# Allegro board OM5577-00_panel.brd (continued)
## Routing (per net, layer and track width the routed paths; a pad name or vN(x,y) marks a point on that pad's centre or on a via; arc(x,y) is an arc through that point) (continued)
A_1_I2C_SCL: length 42.9
  IS1 w0.15: v2(32.2,174.1) 31.65,174.65 28.2,174.65 27.2,175.65 v3(27.2,175.8)
  IS2 w0.5: A_1_TB3.2 8.66,178.24 9.6,177.3 9.6,176.05 12.3,173.35 31.45,173.35 v2(32.2,174.1) 37.9,174.1 40.01,176.21 A_1_TB2.2
A_1_I2C_SDA: length 39
  TOP w0.2: v2(28.3,175.4) 28.3,175.6 27.6,176.3 A_1_U1.C1
  IS2 w0.5: A_1_TB3.3 9.57,180.78 15.1,175.25 21.7,175.25 21.95,175.5 28.2,175.5 v2(28.3,175.4) 30.5,175.4 31,174.9 34.55,174.9 38.4,178.75 A_1_TB2.3
A_1_IRQ: length 39.8
  TOP w0.2: A_1_U1.D1 28,176.8 28.3,176.5 v2(28.3,176.6)
  IS2 w0.5: A_1_TB2.4 38.84,181.29 33.5,175.95 31.35,175.95 30.8,176.5 28.4,176.5 v2(28.3,176.6) 28.2,176.5 22.25,176.5 21.8,176.95 16,176.95 9.63,183.32 A_1_TB3.4
A_1_N2189999: length 7.7
  TOP w0.5: 28.1,186.27 28.1,187.8 A_1_C50.1 A_1_C17.1 A_1_R55.1 ; 28.1,186.27 A_1_C54.2 ; 28.1,186.27 A_1_C15.2 A_1_R53.2
A_1_N2190055: length 7.8
  TOP w0.5: A_1_R54.2 A_1_C16.2 23.3,186.27 ; 23.3,186.27 23.3,187.8 A_1_C51.2 A_1_C18.2 A_1_R56.1 ; 23.3,186.27 A_1_C55.2
A_1_N2190079: length 6.3
  TOP w0.5: A_1_C54.1 28.15,184.7 ; 28.15,184.7 28.15,183.1 A_1_R1.1 A_1_C13.1 28.04,181.56 A_1_L1.2 ; 28.15,184.7 A_1_C15.1
A_1_N2190159: length 11.7
  TOP w0.5: A_1_TB1.3 21.59,194.2 A_1_R73.1 arc(20.64,191.93) A_1_R56.2 arc(20.04,188.9) 19.95,188.42 A_1_C12.2 A_1_C52.2
A_1_N2190199: length 11.7
  TOP w0.5: A_1_TB1.1 29.81,194.2 29.81,194.4 arc(30.76,191.93) A_1_R55.2 arc(31.36,188.9) 31.45,188.42 A_1_C11.2 A_1_C53.2
A_1_N2190513: length 6.3
  TOP w0.5: 23.25,184.7 23.25,183.2 A_1_R2.2 23.37,181.65 A_1_C14.2 23.36,181.54 23.33,180.05 ; 23.25,184.7 A_1_C55.1 ; 23.25,184.7 A_1_C16.1
A_1_N2190991: length 583.3
  TOP w0.5: v2(24.1,196.5) 7.5,196.5 7.5,232.4 26.05,232.4 27.05,231.5 43.25,231.5 43.25,197.4 8.25,197.4 8.25,231.5 v2(25.7,231.5) ; v2(25.7,233.3) 6.75,233.3 6.75,195.6 24.45,195.6 25.45,196.5 44,196.5 44,232.4 v2(27.3,232.4) ; A_1_L104.2 6,194.7 6,234.2 25.95,234.2 26.95,233.3 44.75,233.3 44.75,195.6 v2(25.7,195.6) ; v2(27.3,234.15) 27.3,234.2 45.5,234.2 45.5,194.7 A_1_L104.1
  BOTTOM w0.5: v2(25.7,195.6) v2(24.1,196.5) ; v2(25.7,233.3) v2(27.3,234.15) ; v2(27.3,232.4) v2(25.7,231.5)
A_1_N2198580: length 7.5
  TOP w0.2: v2(31.1,174.1) 31.1,174.3 30.7,174.7 30.24,174.7 30.21,174.67 ; 30.21,174.67 A_1_R23.1 ; 30.21,174.67 A_1_R24.2
  IS1 w0.15: v3(26.7,175.8) 26.7,175.65 28.25,174.1 v2(31.1,174.1)
A_1_N2222470: length 3.3
  TOP w0.5: A_1_C20.2 A_1_R2.1 21.7,183.2 21.7,184.7 A_1_R54.1
A_1_N2227379: length 3.3
  TOP w0.5: A_1_R53.1 29.7,184.7 29.7,183.1 A_1_R1.2 A_1_C19.2
A_1_N2256986: length 4.6
  TOP w0.25: A_1_U1.A3 26.2,174.6 26.45,174.35 26.75,174.35 27.45,173.65 A_1_C57.1 27.29,172.85 26.95,172.85 26.65,172.55 26.5,172.55 26.23,172.28 A_1_Y1.3
A_1_N2256988: length 4.4
  TOP w0.25: A_1_C56.1 25.11,173.51 A_1_Y1.1 v2(25.18,174.53)
  IS1 w0.25: v3(26.2,176.3) 26.2,176.15 25.7,175.65 25.7,175.05 v2(25.18,174.53)
A_1_N2257197: length 1.7
  TOP w0.2: A_1_R32.2 27.99,174.51 A_1_U1.A1
A_1_N2257995: length 4.2
  TOP w0.25: A_1_C1.1 A_1_C22.1 23.06,174.45 23.45,174.45 v2(23.7,174.7)
  IS1 w0.25: v2(23.7,174.7) 23.7,175.7 24.3,176.3 v3(24.7,176.3)
A_1_N2259746: length 5
  TOP w0.25: A_1_C10.1 20.14,178 22.8,178 22.91,177.89 A_1_C7.1 A_1_U1.E7
A_1_N2259753: length 1.5
  TOP w0.25: A_1_C8.1 23.01,176.4 23.35,176.4 23.75,176.8 A_1_U1.D7
A_1_N2259760: length 1.9
  TOP w0.25: A_1_U1.F7 23.85,177.8 23.55,178.1 23.55,178.5 23.35,178.7 A_1_C6.1
A_1_PVDD: length 62.1
  TOP w0.2: A_1_R23.2 A_1_C3.1
  TOP w0.25: A_1_C2.1 23.35,175.3 23.65,175.6 23.65,176 23.95,176.3 A_1_U1.C7 ; A_1_U1.G1 27.5,178.3 27.9,178.7 A_1_C21.1 A_1_C9.1
  TOP w0.3: A_1_U1.G2 A_1_U1.G1
  TOP w0.5: v2(33.35,172.9) 33.35,176.7 32.35,177.7 v2(31.7,177.7)
  IS1 w0.25: v3(29.35,176.7) v3(29.05,176.7) 28.95,176.7 28.89,176.76 28.89,176.84 28.54,177.19 27.98,177.19 27.6,176.8 v3(26.2,176.8)
  IS1 w0.3: v3(29.35,176.7) 29.35,177.4 29.05,177.7 v3(28.65,177.7) v3(28.35,177.7) ; v3(22.75,175.1) v3(22.75,175.5) 20.65,175.5 20.05,174.9 v2(20.05,171.65)
  IS1 w0.5: v3(29.35,176.7) 30.55,176.7 31.55,177.7 v2(31.7,177.7)
  IS2 w0.5: A_1_TB3.1 11.85,171.65 v2(20.05,171.65) 32.1,171.65 v2(33.35,172.9) 40.16,172.9 A_1_TB2.1
A_1_RXN: length 7.5
  TOP w0.5: v2(20.66,179.55) 20.66,179.55 20.66,179.61 21.16,180.11 A_1_C20.1
  IS1 w0.15: v2(20.66,179.55) 20.66,179.05 21.96,177.75 24.13,177.75 24.58,178.2 25,178.2 25.2,178 v3(25.2,177.8)
A_1_RXP: length 9
  TOP w0.5: 29.6,180.06 30.39,180.06 v2(30.85,179.6)
  IS1 w0.15: v3(24.7,177.8) 24.7,177.6 24.9,177.4 25.5,177.4 25.7,177.6 25.7,177.95 25.95,178.2 26.9,178.2 27.4,178.7 29.95,178.7 v2(30.85,179.6)
A_1_TX1: length 1.8
  TOP w0.2: A_1_U1.G3 26.46,178.86
  TOP w0.25: 26.46,178.86 26.47,179.25
  TOP w0.5: 26.47,179.25 26.49,180.05
A_1_TX2: length 1.8
  TOP w0.2: A_1_U1.G5 24.94,178.86
  TOP w0.25: 24.94,178.86 24.93,179.25
  TOP w0.5: 24.93,179.25 A_1_L2.1
A_1_VEN: length 44.7
  TOP w0.2: v3(27.75,177.8) 27.75,177.55 27.5,177.3 A_1_U1.E1
  IS1 w0.2: v2(32.15,178.85) 31.6,178.3 28.25,178.3 v3(27.75,177.8)
  IS2 w0.5: A_1_TB3.5 9.34,185.86 16.75,178.45 22.2,178.45 22.85,177.8 29.45,177.8 30.1,178.45 31.75,178.45 v2(32.15,178.85) 34.25,178.85 39.23,183.83 A_1_TB2.5
A_2_ANT1: length 13.9
  TOP w0.2: A_2_U1.G7 71.43,178.3 v3(71.43,178.32)
  TOP w0.5: v2(79.95,183.05) 80.2,183.3 A_2_C53.1 A_2_C11.1
  IS1 w0.15: v3(71.43,178.32) 71.61,178.5 73.85,178.5 74.4,179.05 76.25,179.05 79.95,182.75 v2(79.95,183.05)
A_2_ANT2: length 11.5
  TOP w0.2: A_2_U1.G6 71.9,178.35 71.9,178.5 71.4,179 v3(71.2,179)
  TOP w0.5: v2(65.95,183.05) 65.7,183.3 A_2_C52.1 A_2_C12.1
  IS1 w0.15: v2(65.95,183.05) 65.95,182.8 69.75,179 v3(71.2,179)
A_2_GND: length 200.9
  TOP w0.2: v2(72.95,179.05) 72.95,181.6 ; v3(74.15,174.85) v3(75.1,173.9) 75.51,173.49 A_2_R32.1
  TOP w0.3: 62.55,190.77 A_2_SH1.7 ; A_2_SH1.7 60.92,191.9 ; A_2_SH1.7 64.18,191.9 ; 57.22,176.8 A_2_SH1.1 ; A_2_SH1.1 58.35,175.17 ; A_2_SH1.1 58.35,178.43 ; A_2_SH1.1 59.48,176.8 ; 78.14,176.7 A_2_C3.2 77.46,177.43 ; 75.8,172.81 A_2_R32.1 76.53,173.49 ; 68.46,178.7 A_2_C6.2 ; A_2_C14.1 72.25,182.49 ; 75.25,190.77 A_2_SH1.6 ; A_2_SH1.6 73.62,191.9 ; A_2_SH1.6 76.88,191.9 ; 83.82,188.6 A_2_SH1.5 ; A_2_SH1.5 86.08,188.6 ; A_2_SH1.5 84.95,190.23 ; A_2_SH1.5 84.95,186.97 ; 84.95,174.27 A_2_SH1.4 ; A_2_SH1.4 84.95,177.53 ; A_2_SH1.4 83.82,175.9 ; A_2_SH1.4 86.08,175.9 ; A_2_SH1.8 59.48,189.5 ; A_2_SH1.8 58.35,191.13 ; A_2_SH1.8 57.22,189.5 ; A_2_SH1.8 58.35,187.87 ; A_2_C21.2 77.44,178.7 ; 77.45,172.96 A_2_R24.1 76.72,173.64 ; 75.43,171.99 A_2_C57.2 74.7,171.31 ; A_2_TB3.6 55.05,189.78 ; A_2_TB3.6 56.43,188.4 ; A_2_TB3.6 53.67,188.4 ; 89.56,186.37 A_2_TB2.6 86.8,186.37 ; 68.46,177.3 A_2_C7.2 ; 68.46,175.3 A_2_C2.2 ; v3(72.95,176.3) A_2_U1.D4 ; 72.42,171.42 A_2_Y1.2 ; 68.46,174.3 A_2_C22.2 ; A_2_SH1.2 64.85,171.43 ; A_2_SH1.2 66.48,170.3 ; A_2_SH1.2 63.22,170.3 ; 69.14,172.57 A_2_C1.2 68.46,173.3 ; A_2_C10.2 67.93,176.79 ; A_2_C10.2 67.2,176.11 ; A_2_C10.2 66.47,176.79 ; A_2_C9.2 77.44,177.7 ; 68.46,176.3 A_2_C8.2 ; A_2_SH1.3 79.18,170.3 ; A_2_SH1.3 75.92,170.3 ; A_2_SH1.3 77.55,171.43 ; A_2_C13.2 73.68,182.49 ; 71.25,171.81 A_2_C56.2 70.52,172.49 ; A_2_U1.G4 v2(72.95,179.05)
  TOP w0.4: 72.95,187.8 72.95,186.7
  TOP w0.5: A_2_C18.1 A_2_C17.2 ; A_2_C18.1 72.25,190.6 ; A_2_C18.1 A_2_C51.1 A_2_C50.2 A_2_C17.2 ; A_2_C17.2 73.68,190.6 ; A_2_C14.1 A_2_C13.2
  IS1 w0.3: A_2_SH1.4 86.08,175.9 ; A_2_SH1.4 84.95,174.77 ; A_2_SH1.4 83.82,175.9 ; A_2_SH1.4 84.95,177.03 ; A_2_SH1.6 76.38,191.9 ; A_2_SH1.6 75.25,190.77 ; A_2_SH1.6 74.12,191.9 ; 76.42,170.3 A_2_SH1.3 ; A_2_SH1.3 78.68,170.3 ; A_2_SH1.3 77.55,171.43 ; A_2_TB3.6 55.05,189.73 ; A_2_TB3.6 53.72,188.4 ; A_2_TB3.6 56.38,188.4 ; A_2_SH1.8 59.48,189.5 ; A_2_SH1.8 57.22,189.5 ; A_2_SH1.8 58.35,188.37 ; A_2_SH1.8 58.35,190.63 ; 62.55,190.77 A_2_SH1.7 ; A_2_SH1.7 61.42,191.9 ; A_2_SH1.7 63.68,191.9 ; 83.82,188.6 A_2_SH1.5 ; A_2_SH1.5 84.95,189.73 ; A_2_SH1.5 84.95,187.47 ; A_2_SH1.5 86.08,188.6 ; 58.35,175.67 A_2_SH1.1 ; A_2_SH1.1 58.35,177.93 ; A_2_SH1.1 59.48,176.8 ; A_2_SH1.1 57.22,176.8 ; A_2_SH1.2 64.85,171.43 ; A_2_SH1.2 63.72,170.3 ; A_2_SH1.2 65.98,170.3 ; 86.85,186.37 A_2_TB2.6 89.51,186.37
  IS2 w0.3: A_2_SH1.6 76.38,191.9 ; A_2_SH1.6 74.12,191.9 ; A_2_SH1.6 75.25,190.77 ; 84.95,174.77 A_2_SH1.4 ; A_2_SH1.4 84.95,177.03 ; A_2_SH1.4 83.82,175.9 ; A_2_SH1.4 86.08,175.9 ; A_2_SH1.5 86.08,188.6 ; A_2_SH1.5 84.95,189.73 ; A_2_SH1.5 84.95,187.47 ; A_2_SH1.5 83.82,188.6 ; A_2_SH1.8 59.48,189.5 ; A_2_SH1.8 58.35,188.37 ; A_2_SH1.8 57.22,189.5 ; A_2_SH1.8 58.35,190.63 ; 86.85,186.37 A_2_TB2.6 89.51,186.37 ; 53.72,188.4 A_2_TB3.6 ; A_2_TB3.6 56.38,188.4 ; A_2_TB3.6 55.05,189.73 ; 76.42,170.3 A_2_SH1.3 78.68,170.3 ; 61.42,191.9 A_2_SH1.7 ; A_2_SH1.7 62.55,190.77 ; A_2_SH1.7 63.68,191.9 ; A_2_SH1.1 59.48,176.8 ; A_2_SH1.1 58.35,177.93 ; A_2_SH1.1 58.35,175.67 ; 63.72,170.3 A_2_SH1.2 65.98,170.3
  BOTTOM w0.3: A_2_SH1.2 66.48,170.3 ; A_2_SH1.2 63.22,170.3 ; A_2_SH1.2 64.85,171.43 ; 83.82,188.6 A_2_SH1.5 ; A_2_SH1.5 86.08,188.6 ; A_2_SH1.5 84.95,190.23 ; A_2_SH1.5 84.95,186.97 ; A_2_SH1.3 77.55,171.43 ; A_2_SH1.3 79.18,170.3 ; A_2_SH1.3 75.92,170.3 ; 62.55,190.77 A_2_SH1.7 ; A_2_SH1.7 60.92,191.9 ; A_2_SH1.7 64.18,191.9 ; A_2_SH1.8 59.48,189.5 ; A_2_SH1.8 58.35,191.13 ; A_2_SH1.8 57.22,189.5 ; A_2_SH1.8 58.35,187.87 ; A_2_TB3.6 55.05,189.78 ; A_2_TB3.6 56.43,188.4 ; A_2_TB3.6 53.67,188.4 ; A_2_SH1.6 76.88,191.9 ; A_2_SH1.6 73.62,191.9 ; A_2_SH1.6 75.25,190.77 ; A_2_SH1.4 84.95,177.53 ; A_2_SH1.4 84.95,174.27 ; A_2_SH1.4 83.82,175.9 ; A_2_SH1.4 86.08,175.9 ; A_2_SH1.1 59.48,176.8 ; A_2_SH1.1 57.22,176.8 ; A_2_SH1.1 58.35,178.43 ; A_2_SH1.1 58.35,175.17 ; 86.8,186.37 A_2_TB2.6 89.56,186.37
  vias: v2(53.35,189.85) v2(53.35,187.35) v2(53.35,184.85) v2(53.35,182.35) v2(53.35,179.85) v2(53.35,177.35) v2(53.35,174.85) v2(53.35,172.35) v2(53.35,169.85) v2(54.75,173.5) v2(54.75,171) v2(55.9,172.25) v2(55.85,169.85) v2(56.65,190.35) v2(56.85,186.75) v2(56.85,184.4) v2(56.85,182) v2(56.85,179.05) v2(56.85,175) v2(57.05,170.9) v2(57.2,192.55) v2(58.35,191.85) v2(58.35,187.3) v2(58.35,185.5) v2(58.35,183) v2(58.35,180.55) v2(58.35,173.5) v2(58.35,170.35) v2(59.2,192.6) v2(59.7,174.65) v2(59.9,190.5) v2(59.9,188) v2(59.9,185.5) v2(59.9,183.6) v2(60.4,172.55) v2(60.5,178.5) v2(60.65,170.3) v2(60.7,175.8) v2(60.85,192.6) v2(60.85,180.5) v2(61.3,189.3) v2(61.3,186.8) v2(61.3,184.3) v2(61.65,174.3) v2(62.4,190.5) v2(62.4,188) v2(62.4,185.5) v2(62.4,183) v2(62.4,181.1) v2(62.4,170.3) v2(62.75,176.15) v2(62.8,172.5) v2(63.15,178.15) v2(63.65,189.25) v2(63.65,186.75) v2(63.65,184.25) v2(63.65,181.75) v2(63.85,179.7) v2(64,174.3) v2(64.25,192.65) v2(64.5,187.55) v2(64.5,185.45) v2(64.7,189.3) v2(64.9,183) v2(64.9,180.5) v2(65.55,192.6) v2(65.45,176) v2(65.45,174.3) v2(65.55,172.5) v2(65.7,177.7) v2(66.2,189.05) v2(66.25,187.45) v2(66.2,181.6) v2(66.25,179.55) v2(66.65,190.7) v2(66.8,170.3) v2(66.9,183.5) v2(67.05,192.65) v2(67.4,180.5) v2(67.9,183.5) v2(67.85,181.75) v2(68.05,172.5) v2(68.15,187.8) v2(68.1,174.3) v2(68.2,176.2) v2(68.65,190.6) v2(69.15,192.55) v2(69.15,172.4) v2(69.4,170.25) v2(69.5,187.8) v2(70.45,191.9) v2(70.95,190.55) v2(71.5,192.6) v2(71.8,170.3) v2(72.25,183.55) v2(72.25,182.7) v2(72.85,191.9) v2(73,190.45) v2(73.55,192.65) v2(73.65,183.55) v2(73.65,182.7) v2(74.35,170.3) v2(75.4,190.5) v2(75.8,172.55) v2(76.45,187.75) v2(76.8,192.65) v2(77.3,190.5) v2(77.7,177.7) v2(77.75,187.75) v2(78,183.5) v2(78.05,181.7) v2(78.05,172.6) v2(78.85,192.6) v2(78.9,180.5) v2(78.9,176.7) v2(79,183.5) v2(79.25,190.5) v2(79.5,173) v2(79.65,189.15) v2(79.65,187.5) v2(79.75,191.9) v2(79.9,181.45) v2(80.7,171.4) v2(80.85,192.6) v2(81,183) v2(81,180.5) v2(80.95,177.85) v2(81.2,189.7) v2(81.3,186.7) v2(81.3,184.6) v2(81.65,170.3) v2(81.75,175.9) v2(82.3,191.9) v2(82.45,190.65) v2(82.45,188.7) v2(82.45,186.2) v2(82.45,183.7) v2(82.45,181.2) v2(82.9,174.85) v2(83.25,179.55) v2(83.2,171.4) v2(83.7,189.95) v2(83.7,187.45) v2(83.7,184.95) v2(83.7,182.45) v2(83.8,192.65) v2(84.9,191.85) v2(84.95,186.3) v2(84.95,183.7) v2(84.95,181.2) v2(84.95,179.1) v2(84.95,172.1) v2(84.95,170.3) v2(86.4,192.65) v2(86.4,190.15) v2(86.4,187.65) v2(86.4,185.15) v2(86.4,182.4) v2(86.4,180) v2(86.45,177.2) v2(86.45,173.8) v2(87.1,171.9) v2(87.1,169.85) v2(89.6,169.85) v2(90.05,177.65) v2(90.05,175.15) v2(90.15,192.65) v2(90.15,190.15) v2(90.15,187.65) v2(90.15,185.15) v2(90.15,182.65) v2(90.15,180.15) v2(90.15,172.95) v2(91.4,191.4) v2(91.4,188.9) v2(91.4,186.4) v2(91.4,183.9) v2(91.4,181.4) v2(91.4,178.9) v2(92.65,192.65) v2(92.65,190.15) v2(92.65,187.65) v2(92.65,185.15) v2(92.65,182.65) v2(92.65,180.15) v2(92.65,177.65) v2(92.65,175.15) v2(92.65,172.65) v3(71.95,176.8) v3(71.95,175.8) v3(72.2,172.4) v3(72.2,171.95) v3(72.45,175.8) v3(72.65,172.4) v3(72.65,171.95) v3(73.25,173.85) v3(73.25,173.3) v3(73.45,177.8) v3(73.7,173.85) v3(73.7,173.3) v3(73.95,177.3) v3(73.95,176.3)
A_2_I2C_SCL: length 42.9
  IS1 w0.15: v3(74.45,175.8) 74.45,175.65 75.45,174.65 78.9,174.65 v2(79.45,174.1)
  IS2 w0.5: A_2_TB3.2 55.91,178.24 56.85,177.3 56.85,176.05 59.55,173.35 78.7,173.35 v2(79.45,174.1) 85.15,174.1 87.26,176.21 A_2_TB2.2
A_2_I2C_SDA: length 39
  TOP w0.2: v2(75.55,175.4) 75.55,175.6 74.85,176.3 A_2_U1.C1
  IS2 w0.5: A_2_TB2.3 85.65,178.75 81.8,174.9 78.25,174.9 77.75,175.4 v2(75.55,175.4) 75.45,175.5 69.2,175.5 68.95,175.25 62.35,175.25 56.82,180.78 A_2_TB3.3
A_2_IRQ: length 39.8
  TOP w0.2: v2(75.55,176.6) 75.55,176.5 75.25,176.8 A_2_U1.D1
  IS2 w0.5: A_2_TB2.4 86.09,181.29 80.75,175.95 78.6,175.95 78.05,176.5 75.65,176.5 v2(75.55,176.6) 75.45,176.5 69.5,176.5 69.05,176.95 63.25,176.95 56.88,183.32 A_2_TB3.4
A_2_N2189999: length 7.7
  TOP w0.5: 75.35,186.27 A_2_C54.2 ; 75.35,186.27 A_2_C15.2 A_2_R53.2 ; 75.35,186.27 75.35,187.8 A_2_C50.1 A_2_C17.1 76.76,189.3
A_2_N2190055: length 7.8
  TOP w0.5: A_2_R56.1 A_2_C18.2 A_2_C51.2 70.55,187.8 70.55,186.27 ; A_2_C55.2 70.55,186.27 ; 70.55,186.27 A_2_C16.2 A_2_R54.2
A_2_N2190079: length 6.3
  TOP w0.5: A_2_L1.2 75.29,181.56 A_2_C13.1 A_2_R1.1 75.4,183.1 75.4,184.7 ; A_2_C54.1 75.4,184.7 ; 75.4,184.7 A_2_C15.1
A_2_N2190159: length 11.7
  TOP w0.5: A_2_TB1.3 68.84,194.2 A_2_R73.1 arc(67.89,191.93) A_2_R56.2 arc(67.29,188.9) 67.2,188.42 A_2_C12.2 A_2_C52.2
A_2_N2190199: length 11.7
  TOP w0.5: A_2_TB1.1 77.06,194.2 77.06,194.4 arc(78.01,191.93) A_2_R55.2 arc(78.61,188.9) 78.7,188.42 A_2_C11.2 A_2_C53.2
A_2_N2190513: length 6.3
  TOP w0.5: A_2_L2.2 70.61,181.54 A_2_C14.2 70.62,181.65 A_2_R2.2 70.5,183.2 70.5,184.7 ; 70.5,184.7 A_2_C16.1 ; 70.5,184.7 A_2_C55.1
A_2_N2190991: length 583.3
  TOP w0.5: v2(74.55,232.4) 91.25,232.4 91.25,196.5 72.7,196.5 71.7,195.6 54,195.6 54,233.3 v2(72.95,233.3) ; A_2_L104.1 92.75,194.7 92.75,234.2 74.55,234.2 v2(74.55,234.15) ; v2(72.95,231.5) 55.5,231.5 55.5,197.4 90.5,197.4 90.5,231.5 74.3,231.5 73.3,232.4 54.75,232.4 54.75,196.5 v2(71.35,196.5) ; v2(72.95,195.6) 92,195.6 92,233.3 74.2,233.3 73.2,234.2 53.25,234.2 53.25,194.7 A_2_L104.2
  BOTTOM w0.5: v2(74.55,232.4) v2(72.95,231.5) ; v2(72.95,195.6) v2(71.35,196.5) ; v2(72.95,233.3) v2(74.55,234.15)
A_2_N2198580: length 7.5
  TOP w0.2: v2(78.35,174.1) 78.35,174.3 77.95,174.7 77.49,174.7 77.46,174.67 ; A_2_R24.2 77.46,174.67 ; 77.46,174.67 A_2_R23.1
  IS1 w0.15: v3(73.95,175.8) 73.95,175.65 75.5,174.1 v2(78.35,174.1)
A_2_N2222470: length 3.3
  TOP w0.5: A_2_C20.2 A_2_R2.1 68.95,183.2 68.95,184.7 A_2_R54.1
A_2_N2227379: length 3.3
  TOP w0.5: A_2_R53.1 76.95,184.7 76.95,183.1 A_2_R1.2 A_2_C19.2
A_2_N2256986: length 4.6
  TOP w0.25: A_2_Y1.3 73.47,172.28 73.75,172.55 73.9,172.55 74.2,172.85 74.54,172.85 A_2_C57.1 74.7,173.65 74,174.35 73.7,174.35 73.45,174.6 A_2_U1.A3
A_2_N2256988: length 4.4
  TOP w0.25: v2(72.42,174.53) A_2_Y1.1 72.36,173.51 A_2_C56.1
  IS1 w0.25: v3(73.45,176.3) 73.45,176.15 72.95,175.65 72.95,175.05 v2(72.42,174.53)
A_2_N2257197: length 1.7
  TOP w0.2: A_2_R32.2 75.24,174.51 A_2_U1.A1
A_2_N2257995: length 4.2
  TOP w0.25: v2(70.95,174.7) 70.7,174.45 70.31,174.45 A_2_C22.1 A_2_C1.1
  IS1 w0.25: v2(70.95,174.7) 70.95,175.7 71.55,176.3 v3(71.95,176.3)
A_2_N2259746: length 5
  TOP w0.25: A_2_C10.1 67.39,178 70.05,178 70.16,177.89 A_2_C7.1 A_2_U1.E7
A_2_N2259753: length 1.5
  TOP w0.25: A_2_C8.1 70.26,176.4 70.6,176.4 71,176.8 A_2_U1.D7
A_2_N2259760: length 1.9
  TOP w0.25: A_2_C6.1 70.6,178.7 70.8,178.5 70.8,178.1 71.1,177.8 A_2_U1.F7
A_2_PVDD: length 62.1
  TOP w0.2: A_2_R23.2 A_2_C3.1
  TOP w0.25: A_2_C9.1 A_2_C21.1 75.15,178.7 74.75,178.3 A_2_U1.G1 ; A_2_U1.C7 71.2,176.3 70.9,176 70.9,175.6 70.6,175.3 A_2_C2.1
  TOP w0.3: A_2_U1.G2 A_2_U1.G1
  TOP w0.5: v2(80.6,172.9) 80.6,176.7 79.6,177.7 v2(78.95,177.7)
  IS1 w0.25: v3(76.6,176.7) v3(76.3,176.7) 76.2,176.7 76.14,176.76 76.14,176.84 75.79,177.19 75.23,177.19 74.85,176.8 v3(73.45,176.8)
  IS1 w0.3: v3(75.6,177.7) v3(75.9,177.7) 76.3,177.7 76.6,177.4 v3(76.6,176.7) ; v2(67.3,171.65) 67.3,174.9 67.9,175.5 v3(70,175.5) v3(70,175.1)
  IS1 w0.5: v2(78.95,177.7) 78.8,177.7 77.8,176.7 v3(76.6,176.7)
  IS2 w0.5: A_2_TB2.1 87.41,172.9 v2(80.6,172.9) 79.35,171.65 v2(67.3,171.65) 59.1,171.65 A_2_TB3.1
A_2_RXN: length 7.5
  TOP w0.5: A_2_C20.1 68.41,180.11 67.91,179.61 67.91,179.55 v2(67.91,179.55)
  IS1 w0.15: v2(67.91,179.55) 67.91,179.05 69.21,177.75 71.38,177.75 71.83,178.2 72.25,178.2 72.45,178 v3(72.45,177.8)
A_2_RXP: length 9
  TOP w0.5: v2(78.1,179.6) 77.64,180.06 76.85,180.06
  IS1 w0.15: v2(78.1,179.6) 77.2,178.7 74.65,178.7 74.15,178.2 73.2,178.2 72.95,177.95 72.95,177.6 72.75,177.4 72.15,177.4 71.95,177.6 v3(71.95,177.8)
A_2_TX1: length 1.8
  TOP w0.2: A_2_U1.G3 73.71,178.86
  TOP w0.25: 73.71,178.86 73.72,179.25
  TOP w0.5: 73.72,179.25 A_2_L1.1
A_2_TX2: length 1.8
  TOP w0.2: A_2_U1.G5 72.19,178.86
  TOP w0.25: 72.19,178.86 72.18,179.25
  TOP w0.5: 72.18,179.25 72.16,180.05
A_2_VEN: length 44.7
  TOP w0.2: v3(75,177.8) 75,177.55 74.75,177.3 A_2_U1.E1
  IS1 w0.2: v3(75,177.8) 75.5,178.3 78.85,178.3 v2(79.4,178.85)
  IS2 w0.5: A_2_TB2.5 86.48,183.83 81.5,178.85 v2(79.4,178.85) 79,178.45 77.35,178.45 76.7,177.8 70.1,177.8 69.45,178.45 64,178.45 56.59,185.86 A_2_TB3.5
A_3_ANT1: length 13.9
  TOP w0.2: A_3_U1.G7 118.68,178.3 v3(118.68,178.32)
  TOP w0.5: A_3_C11.1 A_3_C53.1 127.45,183.3 v2(127.2,183.05)
  IS1 w0.15: v2(127.2,183.05) 127.2,182.75 123.5,179.05 121.65,179.05 121.1,178.5 118.86,178.5 v3(118.68,178.32)
A_3_ANT2: length 11.5
  TOP w0.2: v3(118.45,179) 118.65,179 119.15,178.5 119.15,178.35 A_3_U1.G6
  TOP w0.5: v2(113.2,183.05) 112.95,183.3 A_3_C52.1 A_3_C12.1
  IS1 w0.15: v3(118.45,179) 117,179 113.2,182.8 v2(113.2,183.05)
A_3_GND: length 200.9
  TOP w0.2: A_3_R32.1 122.76,173.49 v3(122.35,173.9) v3(121.4,174.85) ; v2(120.2,179.05) 120.2,181.6
  TOP w0.3: 123.17,170.3 A_3_SH1.3 ; A_3_SH1.3 126.43,170.3 ; A_3_SH1.3 124.8,171.43 ; 115.71,173.3 A_3_C1.2 116.39,172.57 ; A_3_SH1.2 112.1,171.43 ; A_3_SH1.2 113.73,170.3 ; A_3_SH1.2 110.47,170.3 ; 132.2,174.27 A_3_SH1.4 ; A_3_SH1.4 131.07,175.9 ; A_3_SH1.4 133.33,175.9 ; A_3_SH1.4 132.2,177.53 ; 122.68,171.99 A_3_C57.2 121.95,171.31 ; A_3_TB3.6 103.68,188.4 ; A_3_TB3.6 102.3,189.78 ; A_3_TB3.6 100.92,188.4 ; A_3_C10.2 115.18,176.79 ; A_3_C10.2 114.45,176.11 ; A_3_C10.2 113.72,176.79 ; 118.5,171.81 A_3_C56.2 117.77,172.49 ; A_3_C13.2 120.93,182.49 ; A_3_C21.2 124.69,178.7 ; 105.6,175.17 A_3_SH1.1 ; A_3_SH1.1 105.6,178.43 ; A_3_SH1.1 104.47,176.8 ; A_3_SH1.1 106.73,176.8 ; A_3_SH1.5 133.33,188.6 ; A_3_SH1.5 132.2,190.23 ; A_3_SH1.5 131.07,188.6 ; A_3_SH1.5 132.2,186.97 ; 115.71,175.3 A_3_C2.2 ; 115.71,176.3 A_3_C8.2 ; 136.81,186.37 A_3_TB2.6 134.05,186.37 ; 123.97,173.64 A_3_R24.1 124.7,172.96 ; A_3_SH1.7 111.43,191.9 ; A_3_SH1.7 108.17,191.9 ; A_3_SH1.7 109.8,190.77 ; 119.67,171.42 A_3_Y1.2 ; A_3_C14.1 119.5,182.49 ; A_3_SH1.8 105.6,191.13 ; A_3_SH1.8 106.73,189.5 ; A_3_SH1.8 105.6,187.87 ; A_3_SH1.8 104.47,189.5 ; 115.71,177.3 A_3_C7.2 ; A_3_SH1.6 124.13,191.9 ; A_3_SH1.6 120.87,191.9 ; A_3_SH1.6 122.5,190.77 ; 115.71,174.3 A_3_C22.2 ; 124.71,177.43 A_3_C3.2 125.39,176.7 ; A_3_C9.2 124.69,177.7 ; 115.71,178.7 A_3_C6.2 ; A_3_U1.G4 v2(120.2,179.05) ; v3(120.2,176.3) A_3_U1.D4 ; 123.78,173.49 A_3_R32.1 123.05,172.81
  TOP w0.4: 120.2,187.8 120.2,186.7
  TOP w0.5: 120.93,190.6 A_3_C17.2 ; A_3_C17.2 A_3_C50.2 A_3_C51.1 A_3_C18.1 ; A_3_C17.2 A_3_C18.1 ; A_3_C18.1 119.5,190.6 ; A_3_C14.1 A_3_C13.2
  IS1 w0.3: A_3_SH1.6 123.63,191.9 ; A_3_SH1.6 122.5,190.77 ; A_3_SH1.6 121.37,191.9 ; 131.07,175.9 A_3_SH1.4 ; A_3_SH1.4 132.2,177.03 ; A_3_SH1.4 133.33,175.9 ; A_3_SH1.4 132.2,174.77 ; 108.67,191.9 A_3_SH1.7 ; A_3_SH1.7 109.8,190.77 ; A_3_SH1.7 110.93,191.9 ; 104.47,176.8 A_3_SH1.1 ; A_3_SH1.1 106.73,176.8 ; A_3_SH1.1 105.6,175.67 ; A_3_SH1.1 105.6,177.93 ; A_3_SH1.8 105.6,190.63 ; A_3_SH1.8 104.47,189.5 ; A_3_SH1.8 105.6,188.37 ; A_3_SH1.8 106.73,189.5 ; 110.97,170.3 A_3_SH1.2 ; A_3_SH1.2 112.1,171.43 ; A_3_SH1.2 113.23,170.3 ; 100.97,188.4 A_3_TB3.6 ; A_3_TB3.6 102.3,189.73 ; A_3_TB3.6 103.63,188.4 ; 123.67,170.3 A_3_SH1.3 ; A_3_SH1.3 125.93,170.3 ; A_3_SH1.3 124.8,171.43 ; A_3_SH1.5 132.2,189.73 ; A_3_SH1.5 131.07,188.6 ; A_3_SH1.5 132.2,187.47 ; A_3_SH1.5 133.33,188.6 ; 134.1,186.37 A_3_TB2.6 136.76,186.37
  IS2 w0.3: 136.76,186.37 A_3_TB2.6 134.1,186.37 ; A_3_TB3.6 103.63,188.4 ; A_3_TB3.6 102.3,189.73 ; A_3_TB3.6 100.97,188.4 ; A_3_SH1.1 105.6,177.93 ; A_3_SH1.1 105.6,175.67 ; A_3_SH1.1 106.73,176.8 ; 131.07,188.6 A_3_SH1.5 ; A_3_SH1.5 133.33,188.6 ; A_3_SH1.5 132.2,189.73 ; A_3_SH1.5 132.2,187.47 ; 110.97,170.3 A_3_SH1.2 113.23,170.3 ; A_3_SH1.4 133.33,175.9 ; A_3_SH1.4 132.2,177.03 ; A_3_SH1.4 131.07,175.9 ; A_3_SH1.4 132.2,174.77 ; 121.37,191.9 A_3_SH1.6 ; A_3_SH1.6 123.63,191.9 ; A_3_SH1.6 122.5,190.77 ; 125.93,170.3 A_3_SH1.3 123.67,170.3 ; 105.6,188.37 A_3_SH1.8 ; A_3_SH1.8 106.73,189.5 ; A_3_SH1.8 105.6,190.63 ; A_3_SH1.8 104.47,189.5 ; 109.8,190.77 A_3_SH1.7 ; A_3_SH1.7 110.93,191.9 ; A_3_SH1.7 108.67,191.9
  BOTTOM w0.3: A_3_SH1.2 112.1,171.43 ; A_3_SH1.2 113.73,170.3 ; A_3_SH1.2 110.47,170.3 ; A_3_SH1.3 126.43,170.3 ; A_3_SH1.3 124.8,171.43 ; A_3_SH1.3 123.17,170.3 ; A_3_SH1.1 105.6,178.43 ; A_3_SH1.1 105.6,175.17 ; A_3_SH1.1 106.73,176.8 ; A_3_SH1.1 104.47,176.8 ; 100.92,188.4 A_3_TB3.6 ; A_3_TB3.6 103.68,188.4 ; A_3_TB3.6 102.3,189.78 ; 131.07,175.9 A_3_SH1.4 ; A_3_SH1.4 132.2,174.27 ; A_3_SH1.4 133.33,175.9 ; A_3_SH1.4 132.2,177.53 ; 122.5,190.77 A_3_SH1.6 ; A_3_SH1.6 124.13,191.9 ; A_3_SH1.6 120.87,191.9 ; 105.6,187.87 A_3_SH1.8 ; A_3_SH1.8 105.6,191.13 ; A_3_SH1.8 104.47,189.5 ; A_3_SH1.8 106.73,189.5 ; A_3_SH1.5 133.33,188.6 ; A_3_SH1.5 131.07,188.6 ; A_3_SH1.5 132.2,190.23 ; A_3_SH1.5 132.2,186.97 ; 108.17,191.9 A_3_SH1.7 ; A_3_SH1.7 109.8,190.77 ; A_3_SH1.7 111.43,191.9 ; 136.81,186.37 A_3_TB2.6 134.05,186.37
  vias: v2(100.6,189.85) v2(100.6,187.35) v2(100.6,184.85) v2(100.6,182.35) v2(100.6,179.85) v2(100.6,177.35) v2(100.6,174.85) v2(100.6,172.35) v2(100.6,169.85) v2(102,173.5) v2(102,171) v2(103.1,169.85) v2(103.15,172.25) v2(103.9,190.35) v2(104.1,186.75) v2(104.1,184.4) v2(104.1,182) v2(104.1,179.05) v2(104.1,175) v2(104.3,170.9) v2(104.45,192.55) v2(105.6,191.85) v2(105.6,187.3) v2(105.6,185.5) v2(105.6,183) v2(105.6,180.55) v2(105.6,173.5) v2(105.6,170.35) v2(106.45,192.6) v2(106.95,174.65) v2(107.15,190.5) v2(107.15,188) v2(107.15,185.5) v2(107.15,183.6) v2(107.65,172.55) v2(107.75,178.5) v2(107.9,170.3) v2(107.95,175.8) v2(108.1,192.6) v2(108.1,180.5) v2(108.55,189.3) v2(108.55,186.8) v2(108.55,184.3) v2(108.9,174.3) v2(109.65,190.5) v2(109.65,188) v2(109.65,185.5) v2(109.65,183) v2(109.65,181.1) v2(109.65,170.3) v2(110,176.15) v2(110.05,172.5) v2(110.4,178.15) v2(110.9,189.25) v2(110.9,186.75) v2(110.9,184.25) v2(110.9,181.75) v2(111.1,179.7) v2(111.25,174.3) v2(111.5,192.65) v2(111.75,187.55) v2(111.75,185.45) v2(111.95,189.3) v2(112.15,183) v2(112.15,180.5) v2(112.7,176) v2(112.7,174.3) v2(112.8,192.6) v2(112.8,172.5) v2(112.95,177.7) v2(113.45,189.05) v2(113.5,187.45) v2(113.45,181.6) v2(113.5,179.55) v2(113.9,190.7) v2(114.05,170.3) v2(114.15,183.5) v2(114.3,192.65) v2(114.65,180.5) v2(115.1,181.75) v2(115.15,183.5) v2(115.35,174.3) v2(115.3,172.5) v2(115.4,187.8) v2(115.45,176.2) v2(115.9,190.6) v2(116.4,192.55) v2(116.4,172.4) v2(116.65,170.25) v2(116.75,187.8) v2(117.7,191.9) v2(118.2,190.55) v2(118.75,192.6) v2(119.05,170.3) v2(119.5,183.55) v2(119.5,182.7) v2(120.1,191.9) v2(120.25,190.45) v2(120.8,192.65) v2(120.9,183.55) v2(120.9,182.7) v2(121.6,170.3) v2(122.65,190.5) v2(123.05,172.55) v2(123.7,187.75) v2(124.05,192.65) v2(124.55,190.5) v2(125,187.75) v2(124.95,177.7) v2(125.25,183.5) v2(125.3,181.7) v2(125.3,172.6) v2(126.1,192.6) v2(126.25,183.5) v2(126.15,180.5) v2(126.15,176.7) v2(126.5,190.5) v2(126.75,173) v2(126.9,189.15) v2(126.9,187.5) v2(127,191.9) v2(127.15,181.45) v2(127.95,171.4) v2(128.1,192.6) v2(128.25,183) v2(128.25,180.5) v2(128.2,177.85) v2(128.45,189.7) v2(128.55,186.7) v2(128.55,184.6) v2(128.9,170.3) v2(129,175.9) v2(129.55,191.9) v2(129.7,190.65) v2(129.7,188.7) v2(129.7,186.2) v2(129.7,183.7) v2(129.7,181.2) v2(130.15,174.85) v2(130.5,179.55) v2(130.45,171.4) v2(131.05,192.65) v2(130.95,189.95) v2(130.95,187.45) v2(130.95,184.95) v2(130.95,182.45) v2(132.15,191.85) v2(132.2,186.3) v2(132.2,183.7) v2(132.2,181.2) v2(132.2,179.1) v2(132.2,172.1) v2(132.2,170.3) v2(133.65,192.65) v2(133.65,190.15) v2(133.65,187.65) v2(133.65,185.15) v2(133.65,182.4) v2(133.65,180) v2(133.7,177.2) v2(133.7,173.8) v2(134.35,171.9) v2(134.35,169.85) v2(136.85,169.85) v2(137.3,177.65) v2(137.3,175.15) v2(137.4,192.65) v2(137.4,190.15) v2(137.4,187.65) v2(137.4,185.15) v2(137.4,182.65) v2(137.4,180.15) v2(137.4,172.95) v2(138.65,191.4) v2(138.65,188.9) v2(138.65,186.4) v2(138.65,183.9) v2(138.65,181.4) v2(138.65,178.9) v2(139.9,192.65) v2(139.9,190.15) v2(139.9,187.65) v2(139.9,185.15) v2(139.9,182.65) v2(139.9,180.15) v2(139.9,177.65) v2(139.9,175.15) v2(139.9,172.65) v3(119.2,176.8) v3(119.2,175.8) v3(119.45,172.4) v3(119.45,171.95) v3(119.7,175.8) v3(119.9,172.4) v3(119.9,171.95) v3(120.5,173.85) v3(120.5,173.3) v3(120.7,177.8) v3(120.95,173.85) v3(120.95,173.3) v3(121.2,177.3) v3(121.2,176.3)
A_3_I2C_SCL: length 42.9
  IS1 w0.15: v2(126.7,174.1) 126.15,174.65 122.7,174.65 121.7,175.65 v3(121.7,175.8)
  IS2 w0.5: A_3_TB2.2 134.51,176.21 132.4,174.1 v2(126.7,174.1) 125.95,173.35 106.8,173.35 104.1,176.05 104.1,177.3 103.16,178.24 A_3_TB3.2
A_3_I2C_SDA: length 39
  TOP w0.2: A_3_U1.C1 122.1,176.3 122.8,175.6 v2(122.8,175.4)
  IS2 w0.5: A_3_TB2.3 132.9,178.75 129.05,174.9 125.5,174.9 125,175.4 v2(122.8,175.4) 122.7,175.5 116.45,175.5 116.2,175.25 109.6,175.25 104.07,180.78 A_3_TB3.3
A_3_IRQ: length 39.8
  TOP w0.2: A_3_U1.D1 122.5,176.8 122.8,176.5 v2(122.8,176.6)
  IS2 w0.5: A_3_TB3.4 104.13,183.32 110.5,176.95 116.3,176.95 116.75,176.5 122.7,176.5 v2(122.8,176.6) 122.9,176.5 125.3,176.5 125.85,175.95 128,175.95 133.34,181.29 A_3_TB2.4
A_3_N2189999: length 7.7
  TOP w0.5: 122.6,186.27 A_3_C54.2 ; 122.6,186.27 122.6,187.8 A_3_C50.1 A_3_C17.1 A_3_R55.1 ; 122.6,186.27 A_3_C15.2 A_3_R53.2
A_3_N2190055: length 7.8
  TOP w0.5: A_3_R54.2 A_3_C16.2 117.8,186.27 ; 117.8,186.27 A_3_C55.2 ; 117.8,186.27 117.8,187.8 A_3_C51.2 A_3_C18.2 A_3_R56.1
A_3_N2190079: length 6.3
  TOP w0.5: 122.65,184.7 A_3_C15.1 ; 122.65,184.7 A_3_C54.1 ; 122.65,184.7 122.65,183.1 A_3_R1.1 A_3_C13.1 122.54,181.56 A_3_L1.2
A_3_N2190159: length 11.7
  TOP w0.5: A_3_TB1.3 116.09,194.2 A_3_R73.1 arc(115.14,191.93) A_3_R56.2 arc(114.54,188.9) 114.45,188.42 A_3_C12.2 A_3_C52.2
A_3_N2190199: length 11.7
  TOP w0.5: A_3_C53.2 A_3_C11.2 125.95,188.42 arc(125.86,188.9) A_3_R55.2 arc(125.26,191.93) A_3_R75.1 124.31,194.2 A_3_TB1.1
A_3_N2190513: length 6.3
  TOP w0.5: 117.75,184.7 117.75,183.2 A_3_R2.2 117.87,181.65 A_3_C14.2 117.86,181.54 A_3_L2.2 ; 117.75,184.7 A_3_C55.1 ; 117.75,184.7 A_3_C16.1
A_3_N2190991: length 583.3
  TOP w0.5: A_3_L104.1 140,194.7 140,234.2 121.8,234.2 v2(121.8,234.15) ; A_3_L104.2 100.5,194.7 100.5,234.2 120.45,234.2 121.45,233.3 139.25,233.3 139.25,195.6 v2(120.2,195.6) ; v2(118.6,196.5) 102,196.5 102,232.4 120.55,232.4 121.55,231.5 137.75,231.5 137.75,197.4 102.75,197.4 102.75,231.5 v2(120.2,231.5) ; v2(120.2,233.3) 101.25,233.3 101.25,195.6 118.95,195.6 119.95,196.5 138.5,196.5 138.5,232.4 v2(121.8,232.4)
  BOTTOM w0.5: v2(120.2,195.6) v2(118.6,196.5) ; v2(121.8,232.4) v2(120.2,231.5) ; v2(120.2,233.3) v2(121.8,234.15)
A_3_N2198580: length 7.5
  TOP w0.2: A_3_R24.2 124.71,174.67 ; 124.71,174.67 A_3_R23.1 ; 124.71,174.67 124.74,174.7 125.2,174.7 125.6,174.3 v2(125.6,174.1)
  IS1 w0.15: v2(125.6,174.1) 122.75,174.1 121.2,175.65 v3(121.2,175.8)
A_3_N2222470: length 3.3
  TOP w0.5: A_3_C20.2 A_3_R2.1 116.2,183.2 116.2,184.7 A_3_R54.1
A_3_N2227379: length 3.3
  TOP w0.5: A_3_R53.1 124.2,184.7 124.2,183.1 A_3_R1.2 A_3_C19.2
A_3_N2256986: length 4.6
  TOP w0.25: A_3_U1.A3 120.7,174.6 120.95,174.35 121.25,174.35 121.95,173.65 A_3_C57.1 121.79,172.85 121.45,172.85 121.15,172.55 121,172.55 120.72,172.28 120.72,172.22
A_3_N2256988: length 4.4
  TOP w0.25: v2(119.67,174.53) A_3_Y1.1 119.61,173.51 A_3_C56.1
  IS1 w0.25: v3(120.7,176.3) 120.7,176.15 120.2,175.65 120.2,175.05 v2(119.67,174.53)
A_3_N2257197: length 1.7
  TOP w0.2: A_3_R32.2 122.49,174.51 A_3_U1.A1
A_3_N2257995: length 4.2
  TOP w0.25: A_3_C1.1 A_3_C22.1 117.56,174.45 117.95,174.45 v2(118.2,174.7)
  IS1 w0.25: v2(118.2,174.7) 118.2,175.7 118.8,176.3 v3(119.2,176.3)
A_3_N2259746: length 5
  TOP w0.25: A_3_U1.E7 A_3_C7.1 117.41,177.89 117.3,178 114.64,178 A_3_C10.1
A_3_N2259753: length 1.5
  TOP w0.25: A_3_U1.D7 118.25,176.8 117.85,176.4 117.51,176.4 A_3_C8.1
A_3_N2259760: length 1.9
  TOP w0.25: A_3_C6.1 117.85,178.7 118.05,178.5 118.05,178.1 118.35,177.8 A_3_U1.F7
A_3_PVDD: length 62.1
  TOP w0.2: A_3_R23.2 A_3_C3.1
  TOP w0.25: A_3_U1.C7 118.45,176.3 118.15,176 118.15,175.6 117.85,175.3 A_3_C2.1 ; A_3_C9.1 A_3_C21.1 122.4,178.7 122,178.3 A_3_U1.G1
  TOP w0.3: A_3_U1.G2 A_3_U1.G1
  TOP w0.5: v2(126.2,177.7) 126.85,177.7 127.85,176.7 v2(127.85,172.9)
  IS1 w0.25: v3(123.85,176.7) v3(123.55,176.7) 123.45,176.7 123.39,176.76 123.39,176.84 123.04,177.19 122.48,177.19 122.1,176.8 v3(120.7,176.8)
  IS1 w0.3: v3(123.85,176.7) 123.85,177.4 123.55,177.7 v3(123.15,177.7) v3(122.85,177.7) ; v2(114.55,171.65) 114.55,174.9 115.15,175.5 v3(117.25,175.5) v3(117.25,175.1)
  IS1 w0.5: v3(123.85,176.7) 125.05,176.7 126.05,177.7 v2(126.2,177.7)
  IS2 w0.5: A_3_TB3.1 106.35,171.65 v2(114.55,171.65) 126.6,171.65 v2(127.85,172.9) 134.66,172.9 A_3_TB2.1
A_3_RXN: length 7.5
  TOP w0.5: A_3_C20.1 115.66,180.11 115.16,179.61 115.16,179.55 v2(115.16,179.55)
  IS1 w0.15: v2(115.16,179.55) 115.16,179.05 116.46,177.75 118.63,177.75 119.08,178.2 119.5,178.2 119.7,178 v3(119.7,177.8)
A_3_RXP: length 9
  TOP w0.5: v2(125.35,179.6) 124.89,180.06 124.1,180.06
  IS1 w0.15: v3(119.2,177.8) 119.2,177.6 119.4,177.4 120,177.4 120.2,177.6 120.2,177.95 120.45,178.2 121.4,178.2 121.9,178.7 124.45,178.7 v2(125.35,179.6)
A_3_TX1: length 1.8
  TOP w0.2: A_3_U1.G3 120.96,178.86
  TOP w0.25: 120.96,178.86 120.97,179.25
  TOP w0.5: 120.97,179.25 A_3_L1.1
A_3_TX2: length 1.8
  TOP w0.2: A_3_U1.G5 119.44,178.86
  TOP w0.25: 119.44,178.86 119.43,179.25
  TOP w0.5: 119.43,179.25 A_3_L2.1
A_3_VEN: length 44.7
  TOP w0.2: v3(122.25,177.8) 122.25,177.55 122,177.3 A_3_U1.E1
  IS1 w0.2: v2(126.65,178.85) 126.1,178.3 122.75,178.3 v3(122.25,177.8)
  IS2 w0.5: A_3_TB3.5 103.84,185.86 111.25,178.45 116.7,178.45 117.35,177.8 123.95,177.8 124.6,178.45 126.25,178.45 v2(126.65,178.85) 128.75,178.85 133.73,183.83 A_3_TB2.5
A_4_ANT1: length 13.9
  TOP w0.2: v3(165.93,178.32) 165.93,178.3 A_4_U1.G7
  TOP w0.5: v2(174.45,183.05) 174.7,183.3 A_4_C53.1 A_4_C11.1
  IS1 w0.15: v2(174.45,183.05) 174.45,182.75 170.75,179.05 168.9,179.05 168.35,178.5 166.11,178.5 v3(165.93,178.32)
A_4_ANT2: length 11.5
  TOP w0.2: A_4_U1.G6 166.4,178.35 166.4,178.5 165.9,179 v3(165.7,179)
  TOP w0.5: v2(160.45,183.05) 160.2,183.3 A_4_C52.1 A_4_C12.1
  IS1 w0.15: v2(160.45,183.05) 160.45,182.8 164.25,179 v3(165.7,179)
A_4_GND: length 200.9
  TOP w0.2: A_4_R32.1 170.01,173.49 v3(169.6,173.9) v3(168.65,174.85) ; v2(167.45,179.05) 167.45,181.6
  TOP w0.3: 155.42,191.9 A_4_SH1.7 ; A_4_SH1.7 158.68,191.9 ; A_4_SH1.7 157.05,190.77 ; A_4_SH1.3 173.68,170.3 ; A_4_SH1.3 170.42,170.3 ; A_4_SH1.3 172.05,171.43 ; A_4_C14.1 166.75,182.49 ; A_4_C10.2 162.43,176.79 ; A_4_C10.2 161.7,176.11 ; A_4_C10.2 160.97,176.79 ; A_4_SH1.4 179.45,177.53 ; A_4_SH1.4 180.58,175.9 ; A_4_SH1.4 178.32,175.9 ; A_4_SH1.4 179.45,174.27 ; 162.96,178.7 A_4_C6.2 ; A_4_C21.2 171.94,178.7 ; 171.96,177.43 A_4_C3.2 172.64,176.7 ; 165.75,171.81 A_4_C56.2 165.02,172.49 ; 162.96,173.3 A_4_C1.2 163.64,172.57 ; 151.72,189.5 A_4_SH1.8 ; A_4_SH1.8 153.98,189.5 ; A_4_SH1.8 152.85,191.13 ; A_4_SH1.8 152.85,187.87 ; 171.03,173.49 A_4_R32.1 170.3,172.81 ; 162.96,175.3 A_4_C2.2 ; A_4_SH1.6 171.38,191.9 ; A_4_SH1.6 168.12,191.9 ; A_4_SH1.6 169.75,190.77 ; 148.17,188.4 A_4_TB3.6 ; A_4_TB3.6 150.93,188.4 ; A_4_TB3.6 149.55,189.78 ; 162.96,174.3 A_4_C22.2 ; 151.72,176.8 A_4_SH1.1 ; A_4_SH1.1 153.98,176.8 ; A_4_SH1.1 152.85,178.43 ; A_4_SH1.1 152.85,175.17 ; 171.22,173.64 A_4_R24.1 171.95,172.96 ; 166.93,171.42 A_4_Y1.2 ; 184.06,186.37 A_4_TB2.6 181.3,186.37 ; A_4_SH1.2 159.35,171.43 ; A_4_SH1.2 157.72,170.3 ; A_4_SH1.2 160.98,170.3 ; 169.93,171.99 A_4_C57.2 169.2,171.31 ; A_4_C13.2 168.18,182.49 ; A_4_C9.2 171.94,177.7 ; 162.96,176.3 A_4_C8.2 ; v3(167.45,176.3) A_4_U1.D4 ; A_4_SH1.5 179.45,190.23 ; A_4_SH1.5 178.32,188.6 ; A_4_SH1.5 179.45,186.97 ; A_4_SH1.5 180.58,188.6 ; 162.96,177.3 A_4_C7.2 ; A_4_U1.G4 v2(167.45,179.05)
  TOP w0.4: 167.45,187.8 167.45,186.7
  TOP w0.5: A_4_C17.2 A_4_C50.2 A_4_C51.1 A_4_C18.1 ; A_4_C17.2 168.18,190.6 ; A_4_C17.2 A_4_C18.1 ; A_4_C14.1 A_4_C13.2 ; A_4_C18.1 166.75,190.6
  IS1 w0.3: 170.92,170.3 A_4_SH1.3 ; A_4_SH1.3 172.05,171.43 ; A_4_SH1.3 173.18,170.3 ; 152.85,175.67 A_4_SH1.1 ; A_4_SH1.1 152.85,177.93 ; A_4_SH1.1 153.98,176.8 ; A_4_SH1.1 151.72,176.8 ; A_4_SH1.2 160.48,170.3 ; A_4_SH1.2 158.22,170.3 ; A_4_SH1.2 159.35,171.43 ; 179.45,187.47 A_4_SH1.5 ; A_4_SH1.5 180.58,188.6 ; A_4_SH1.5 179.45,189.73 ; A_4_SH1.5 178.32,188.6 ; 184.01,186.37 A_4_TB2.6 181.35,186.37 ; 179.45,174.77 A_4_SH1.4 ; A_4_SH1.4 178.32,175.9 ; A_4_SH1.4 180.58,175.9 ; A_4_SH1.4 179.45,177.03 ; A_4_TB3.6 149.55,189.73 ; A_4_TB3.6 148.22,188.4 ; A_4_TB3.6 150.88,188.4 ; 169.75,190.77 A_4_SH1.6 ; A_4_SH1.6 168.62,191.9 ; A_4_SH1.6 170.88,191.9 ; A_4_SH1.8 153.98,189.5 ; A_4_SH1.8 152.85,190.63 ; A_4_SH1.8 151.72,189.5 ; A_4_SH1.8 152.85,188.37 ; 155.92,191.9 A_4_SH1.7 ; A_4_SH1.7 158.18,191.9 ; A_4_SH1.7 157.05,190.77
  IS2 w0.3: 178.32,175.9 A_4_SH1.4 ; A_4_SH1.4 179.45,177.03 ; A_4_SH1.4 180.58,175.9 ; A_4_SH1.4 179.45,174.77 ; 148.22,188.4 A_4_TB3.6 ; A_4_TB3.6 149.55,189.73 ; A_4_TB3.6 150.88,188.4 ; 157.05,190.77 A_4_SH1.7 ; A_4_SH1.7 155.92,191.9 ; A_4_SH1.7 158.18,191.9 ; 170.92,170.3 A_4_SH1.3 173.18,170.3 ; A_4_SH1.1 153.98,176.8 ; A_4_SH1.1 152.85,175.67 ; A_4_SH1.1 152.85,177.93 ; 151.72,189.5 A_4_SH1.8 ; A_4_SH1.8 152.85,190.63 ; A_4_SH1.8 152.85,188.37 ; A_4_SH1.8 153.98,189.5 ; 160.48,170.3 A_4_SH1.2 158.22,170.3 ; A_4_SH1.6 170.88,191.9 ; A_4_SH1.6 168.62,191.9 ; A_4_SH1.6 169.75,190.77 ; A_4_SH1.5 179.45,189.73 ; A_4_SH1.5 180.58,188.6 ; A_4_SH1.5 178.32,188.6 ; A_4_SH1.5 179.45,187.47 ; 184.01,186.37 A_4_TB2.6 181.35,186.37
  BOTTOM w0.3: A_4_SH1.4 179.45,177.53 ; A_4_SH1.4 178.32,175.9 ; A_4_SH1.4 179.45,174.27 ; A_4_SH1.4 180.58,175.9 ; 170.42,170.3 A_4_SH1.3 ; A_4_SH1.3 172.05,171.43 ; A_4_SH1.3 173.68,170.3 ; A_4_SH1.5 180.58,188.6 ; A_4_SH1.5 179.45,186.97 ; A_4_SH1.5 179.45,190.23 ; A_4_SH1.5 178.32,188.6 ; 152.85,187.87 A_4_SH1.8 ; A_4_SH1.8 151.72,189.5 ; A_4_SH1.8 153.98,189.5 ; A_4_SH1.8 152.85,191.13 ; A_4_SH1.1 152.85,178.43 ; A_4_SH1.1 153.98,176.8 ; A_4_SH1.1 151.72,176.8 ; A_4_SH1.1 152.85,175.17 ; A_4_TB3.6 150.93,188.4 ; A_4_TB3.6 148.17,188.4 ; A_4_TB3.6 149.55,189.78 ; A_4_SH1.6 171.38,191.9 ; A_4_SH1.6 169.75,190.77 ; A_4_SH1.6 168.12,191.9 ; A_4_SH1.2 159.35,171.43 ; A_4_SH1.2 160.98,170.3 ; A_4_SH1.2 157.72,170.3 ; 157.05,190.77 A_4_SH1.7 ; A_4_SH1.7 158.68,191.9 ; A_4_SH1.7 155.42,191.9 ; 181.3,186.37 A_4_TB2.6 184.06,186.37
  vias: v2(147.85,189.85) v2(147.85,187.35) v2(147.85,184.85) v2(147.85,182.35) v2(147.85,179.85) v2(147.85,177.35) v2(147.85,174.85) v2(147.85,172.35) v2(147.85,169.85) v2(149.25,173.5) v2(149.25,171) v2(150.35,169.85) v2(150.4,172.25) v2(151.15,190.35) v2(151.35,186.75) v2(151.35,184.4) v2(151.35,182) v2(151.35,179.05) v2(151.35,175) v2(151.55,170.9) v2(151.7,192.55) v2(152.85,191.85) v2(152.85,187.3) v2(152.85,185.5) v2(152.85,183) v2(152.85,180.55) v2(152.85,173.5) v2(152.85,170.35) v2(153.7,192.6) v2(154.2,174.65) v2(154.4,190.5) v2(154.4,188) v2(154.4,185.5) v2(154.4,183.6) v2(154.9,172.55) v2(155,178.5) v2(155.2,175.8) v2(155.15,170.3) v2(155.35,192.6) v2(155.35,180.5) v2(155.8,189.3) v2(155.8,186.8) v2(155.8,184.3) v2(156.15,174.3) v2(156.9,190.5) v2(156.9,188) v2(156.9,185.5) v2(156.9,183) v2(156.9,181.1) v2(156.9,170.3) v2(157.25,176.15) v2(157.3,172.5) v2(157.65,178.15) v2(158.15,189.25) v2(158.15,186.75) v2(158.15,184.25) v2(158.15,181.75) v2(158.35,179.7) v2(158.5,174.3) v2(158.75,192.65) v2(159,187.55) v2(159,185.45) v2(159.2,189.3) v2(159.4,183) v2(159.4,180.5) v2(159.95,176) v2(159.95,174.3) v2(160.05,192.6) v2(160.05,172.5) v2(160.2,177.7) v2(160.7,189.05) v2(160.7,181.6) v2(160.75,187.45) v2(160.75,179.55) v2(161.15,190.7) v2(161.3,170.3) v2(161.4,183.5) v2(161.55,192.65) v2(161.9,180.5) v2(162.35,181.75) v2(162.4,183.5) v2(162.6,174.3) v2(162.55,172.5) v2(162.65,187.8) v2(162.7,176.2) v2(163.15,190.6) v2(163.65,192.55) v2(163.65,172.4) v2(163.9,170.25) v2(164,187.8) v2(164.95,191.9) v2(165.45,190.55) v2(166,192.6) v2(166.3,170.3) v2(166.75,183.55) v2(166.75,182.7) v2(167.35,191.9) v2(167.5,190.45) v2(168.05,192.65) v2(168.15,183.55) v2(168.15,182.7) v2(168.85,170.3) v2(169.9,190.5) v2(170.3,172.55) v2(170.95,187.75) v2(171.3,192.65) v2(171.8,190.5) v2(172.25,187.75) v2(172.2,177.7) v2(172.5,183.5) v2(172.55,181.7) v2(172.55,172.6) v2(173.35,192.6) v2(173.4,180.5) v2(173.4,176.7) v2(173.5,183.5) v2(173.75,190.5) v2(174,173) v2(174.25,191.9) v2(174.15,189.15) v2(174.15,187.5) v2(174.4,181.45) v2(175.2,171.4) v2(175.35,192.6) v2(175.45,177.85) v2(175.5,183) v2(175.5,180.5) v2(175.7,189.7) v2(175.8,186.7) v2(175.8,184.6) v2(176.25,175.9) v2(176.15,170.3) v2(176.8,191.9) v2(176.95,190.65) v2(176.95,188.7) v2(176.95,186.2) v2(176.95,183.7) v2(176.95,181.2) v2(177.4,174.85) v2(177.7,171.4) v2(177.75,179.55) v2(178.2,189.95) v2(178.2,187.45) v2(178.2,184.95) v2(178.2,182.45) v2(178.3,192.65) v2(179.4,191.85) v2(179.45,186.3) v2(179.45,183.7) v2(179.45,181.2) v2(179.45,179.1) v2(179.45,172.1) v2(179.45,170.3) v2(180.9,192.65) v2(180.9,190.15) v2(180.9,187.65) v2(180.9,185.15) v2(180.9,182.4) v2(180.9,180) v2(180.95,177.2) v2(180.95,173.8) v2(181.6,171.9) v2(181.6,169.85) v2(184.1,169.85) v2(184.55,177.65) v2(184.55,175.15) v2(184.65,192.65) v2(184.65,190.15) v2(184.65,187.65) v2(184.65,185.15) v2(184.65,182.65) v2(184.65,180.15) v2(184.65,172.95) v2(185.9,191.4) v2(185.9,188.9) v2(185.9,186.4) v2(185.9,183.9) v2(185.9,181.4) v2(185.9,178.9) v2(187.15,192.65) v2(187.15,190.15) v2(187.15,187.65) v2(187.15,185.15) v2(187.15,182.65) v2(187.15,180.15) v2(187.15,177.65) v2(187.15,175.15) v2(187.15,172.65) v3(166.45,176.8) v3(166.45,175.8) v3(166.7,172.4) v3(166.7,171.95) v3(166.95,175.8) v3(167.15,172.4) v3(167.15,171.95) v3(167.75,173.85) v3(167.75,173.3) v3(167.95,177.8) v3(168.2,173.85) v3(168.2,173.3) v3(168.45,177.3) v3(168.45,176.3)
A_4_I2C_SCL: length 42.9
  IS1 w0.15: v2(173.95,174.1) 173.4,174.65 169.95,174.65 168.95,175.65 v3(168.95,175.8)
  IS2 w0.5: A_4_TB3.2 150.41,178.24 151.35,177.3 151.35,176.05 154.05,173.35 173.2,173.35 v2(173.95,174.1) 179.65,174.1 181.76,176.21 A_4_TB2.2
A_4_I2C_SDA: length 39
  TOP w0.2: v2(170.05,175.4) 170.05,175.6 169.35,176.3 A_4_U1.C1
  IS2 w0.5: A_4_TB3.3 151.32,180.78 156.85,175.25 163.45,175.25 163.7,175.5 169.95,175.5 v2(170.05,175.4) 172.25,175.4 172.75,174.9 176.3,174.9 180.15,178.75 A_4_TB2.3
A_4_IRQ: length 39.8
  TOP w0.2: v2(170.05,176.6) 170.05,176.5 169.75,176.8 A_4_U1.D1
  IS2 w0.5: A_4_TB3.4 151.38,183.32 157.75,176.95 163.55,176.95 164,176.5 169.95,176.5 v2(170.05,176.6) 170.15,176.5 172.55,176.5 173.1,175.95 175.25,175.95 180.59,181.29 A_4_TB2.4
A_4_N2189999: length 7.7
  TOP w0.5: A_4_R55.1 A_4_C17.1 A_4_C50.1 169.85,187.8 169.85,186.27 ; 169.85,186.27 A_4_C54.2 ; 169.85,186.27 A_4_C15.2 A_4_R53.2
A_4_N2190055: length 7.8
  TOP w0.5: A_4_R56.1 A_4_C18.2 A_4_C51.2 165.05,187.8 165.05,186.27 ; A_4_C55.2 165.05,186.27 ; 165.05,186.27 A_4_C16.2 A_4_R54.2
A_4_N2190079: length 6.3
  TOP w0.5: 169.9,184.7 169.9,183.1 A_4_R1.1 A_4_C13.1 169.79,181.56 A_4_L1.2 ; 169.9,184.7 A_4_C15.1 ; 169.9,184.7 A_4_C54.1
A_4_N2190159: length 11.7
  TOP w0.5: A_4_TB1.3 163.34,194.2 163.34,194.4 arc(162.39,191.93) A_4_R56.2 arc(161.79,188.9) 161.7,188.42 A_4_C12.2 A_4_C52.2
A_4_N2190199: length 11.7
  TOP w0.5: A_4_C53.2 A_4_C11.2 173.2,188.42 arc(173.11,188.9) 172.84,189.3 arc(172.51,191.93) A_4_R75.1 171.56,194.2 A_4_TB1.1
A_4_N2190513: length 6.3
  TOP w0.5: A_4_C55.1 165,184.7 ; 165,184.7 165,183.2 A_4_R2.2 165.12,181.65 A_4_C14.2 165.11,181.54 A_4_L2.2 ; 165,184.7 A_4_C16.1
A_4_N2190991: length 583.3
  TOP w0.5: A_4_L104.2 147.75,194.7 147.75,234.2 167.7,234.2 168.7,233.3 186.5,233.3 186.5,195.6 v2(167.45,195.6) ; v2(169.05,234.15) 169.05,234.2 187.25,234.2 187.25,194.7 A_4_L104.1 ; v2(165.85,196.5) 149.25,196.5 149.25,232.4 167.8,232.4 168.8,231.5 185,231.5 185,197.4 150,197.4 150,231.5 v2(167.45,231.5) ; v2(169.05,232.4) 185.75,232.4 185.75,196.5 167.2,196.5 166.2,195.6 148.5,195.6 148.5,233.3 v2(167.45,233.3)
  BOTTOM w0.5: v2(167.45,195.6) v2(165.85,196.5) ; v2(169.05,232.4) v2(167.45,231.5) ; v2(167.45,233.3) v2(169.05,234.15)
A_4_N2198580: length 7.5
  TOP w0.2: 171.96,174.67 171.99,174.7 172.45,174.7 172.85,174.3 v2(172.85,174.1) ; 171.96,174.67 A_4_R23.1 ; 171.96,174.67 A_4_R24.2
  IS1 w0.15: v2(172.85,174.1) 170,174.1 168.45,175.65 v3(168.45,175.8)
A_4_N2222470: length 3.3
  TOP w0.5: A_4_R54.1 163.45,184.7 163.45,183.2 A_4_R2.1 A_4_C20.2
A_4_N2227379: length 3.3
  TOP w0.5: A_4_R53.1 171.45,184.7 171.45,183.1 A_4_R1.2 A_4_C19.2
A_4_N2256986: length 4.6
  TOP w0.25: A_4_U1.A3 167.95,174.6 168.2,174.35 168.5,174.35 169.2,173.65 A_4_C57.1 169.04,172.85 168.7,172.85 168.4,172.55 168.25,172.55 167.97,172.28 A_4_Y1.3
A_4_N2256988: length 4.4
  TOP w0.25: v2(166.93,174.53) A_4_Y1.1 166.86,173.51 A_4_C56.1
  IS1 w0.25: v2(166.93,174.53) 167.45,175.05 167.45,175.65 167.95,176.15 v3(167.95,176.3)
A_4_N2257197: length 1.7
  TOP w0.2: A_4_U1.A1 169.74,174.51 A_4_R32.2
A_4_N2257995: length 4.2
  TOP w0.25: A_4_C1.1 A_4_C22.1 164.81,174.45 165.2,174.45 v2(165.45,174.7)
  IS1 w0.25: v2(165.45,174.7) 165.45,175.7 166.05,176.3 v3(166.45,176.3)
A_4_N2259746: length 5
  TOP w0.25: A_4_C10.1 161.89,178 164.55,178 164.66,177.89 A_4_C7.1 A_4_U1.E7
A_4_N2259753: length 1.5
  TOP w0.25: A_4_C8.1 164.76,176.4 165.1,176.4 165.5,176.8 A_4_U1.D7
A_4_N2259760: length 1.9
  TOP w0.25: A_4_C6.1 165.1,178.7 165.3,178.5 165.3,178.1 165.6,177.8 A_4_U1.F7
A_4_PVDD: length 62.1
  TOP w0.2: A_4_R23.2 A_4_C3.1
  TOP w0.25: A_4_C9.1 A_4_C21.1 169.65,178.7 169.25,178.3 A_4_U1.G1 ; A_4_U1.C7 165.7,176.3 165.4,176 165.4,175.6 165.1,175.3 A_4_C2.1
  TOP w0.3: A_4_U1.G2 A_4_U1.G1
  TOP w0.5: v2(175.1,172.9) 175.1,176.7 174.1,177.7 v2(173.45,177.7)
  IS1 w0.25: v3(171.1,176.7) v3(170.8,176.7) 170.7,176.7 170.63,176.76 170.63,176.84 170.29,177.19 169.74,177.19 169.35,176.8 v3(167.95,176.8)
  IS1 w0.3: v3(170.1,177.7) v3(170.4,177.7) 170.8,177.7 171.1,177.4 v3(171.1,176.7) ; v2(161.8,171.65) 161.8,174.9 162.4,175.5 v3(164.5,175.5) v3(164.5,175.1)
  IS1 w0.5: v2(173.45,177.7) 173.3,177.7 172.3,176.7 v3(171.1,176.7)
  IS2 w0.5: A_4_TB3.1 153.6,171.65 v2(161.8,171.65) 173.85,171.65 v2(175.1,172.9) 181.91,172.9 A_4_TB2.1
A_4_RXN: length 7.5
  TOP w0.5: A_4_C20.1 162.91,180.11 162.41,179.61 162.41,179.55 v2(162.41,179.55)
  IS1 w0.15: v3(166.95,177.8) 166.95,178 166.75,178.2 166.33,178.2 165.88,177.75 163.71,177.75 162.41,179.05 v2(162.41,179.55)
A_4_RXP: length 9
  TOP w0.5: 171.35,180.06 172.14,180.06 v2(172.6,179.6)
  IS1 w0.15: v2(172.6,179.6) 171.7,178.7 169.15,178.7 168.65,178.2 167.7,178.2 167.45,177.95 167.45,177.6 167.25,177.4 166.65,177.4 166.45,177.6 v3(166.45,177.8)
A_4_TX1: length 1.8
  TOP w0.2: A_4_U1.G3 168.21,178.86
  TOP w0.25: 168.21,178.86 168.22,179.25
  TOP w0.5: 168.22,179.25 A_4_L1.1
A_4_TX2: length 1.8
  TOP w0.2: A_4_U1.G5 166.69,178.86
  TOP w0.25: 166.69,178.86 166.68,179.25
  TOP w0.5: 166.68,179.25 A_4_L2.1
A_4_VEN: length 44.7
  TOP w0.2: A_4_U1.E1 169.25,177.3 169.5,177.55 v3(169.5,177.8)
  IS1 w0.2: v2(173.9,178.85) 173.35,178.3 170,178.3 v3(169.5,177.8)
  IS2 w0.5: A_4_TB2.5 180.98,183.83 176,178.85 v2(173.9,178.85) 173.5,178.45 171.85,178.45 171.2,177.8 164.6,177.8 163.95,178.45 158.5,178.45 151.09,185.86 A_4_TB3.5
A_5_ANT1: length 13.9
  TOP w0.2: v3(213.18,178.32) 213.18,178.3 A_5_U1.G7
  TOP w0.5: v2(221.7,183.05) 221.95,183.3 A_5_C53.1 A_5_C11.1
  IS1 w0.15: v2(221.7,183.05) 221.7,182.75 218,179.05 216.15,179.05 215.6,178.5 213.36,178.5 v3(213.18,178.32)
A_5_ANT2: length 11.5
  TOP w0.2: A_5_U1.G6 213.65,178.35 213.65,178.5 213.15,179 v3(212.95,179)
  TOP w0.5: A_5_C12.1 A_5_C52.1 207.45,183.3 v2(207.7,183.05)
  IS1 w0.15: v3(212.95,179) 211.5,179 207.7,182.8 v2(207.7,183.05)
A_5_GND: length 200.9
  TOP w0.2: v2(214.7,179.05) 214.7,181.6 ; A_5_R32.1 217.26,173.49 v3(216.85,173.9) v3(215.9,174.85)
  TOP w0.3: v3(214.7,176.3) A_5_U1.D4 ; 218.28,173.49 A_5_R32.1 217.55,172.81 ; A_5_SH1.2 206.6,171.43 ; A_5_SH1.2 208.23,170.3 ; A_5_SH1.2 204.97,170.3 ; A_5_SH1.6 218.63,191.9 ; A_5_SH1.6 217,190.77 ; A_5_SH1.6 215.37,191.9 ; A_5_SH1.3 220.93,170.3 ; A_5_SH1.3 217.67,170.3 ; A_5_SH1.3 219.3,171.43 ; 208.22,176.79 A_5_C10.2 ; A_5_C10.2 208.95,176.11 ; A_5_C10.2 209.68,176.79 ; A_5_TB3.6 196.8,189.78 ; A_5_TB3.6 198.18,188.4 ; A_5_TB3.6 195.42,188.4 ; 231.31,186.37 A_5_TB2.6 228.55,186.37 ; A_5_SH1.4 227.83,175.9 ; A_5_SH1.4 226.7,177.53 ; A_5_SH1.4 225.57,175.9 ; A_5_SH1.4 226.7,174.27 ; 210.21,176.3 A_5_C8.2 ; A_5_SH1.1 201.23,176.8 ; A_5_SH1.1 200.1,175.17 ; A_5_SH1.1 200.1,178.43 ; A_5_SH1.1 198.97,176.8 ; A_5_U1.G4 v2(214.7,179.05) ; 216.45,171.31 A_5_C57.2 217.18,171.99 ; A_5_C9.2 219.19,177.7 ; 226.7,186.97 A_5_SH1.5 ; A_5_SH1.5 227.83,188.6 ; A_5_SH1.5 226.7,190.23 ; A_5_SH1.5 225.57,188.6 ; 212.27,172.49 A_5_C56.2 213,171.81 ; 210.21,173.3 A_5_C1.2 210.89,172.57 ; 214.18,171.42 214.18,172.22 ; 210.21,175.3 A_5_C2.2 ; 210.21,174.3 A_5_C22.2 ; A_5_SH1.7 205.93,191.9 ; A_5_SH1.7 204.3,190.77 ; A_5_SH1.7 202.67,191.9 ; 218.47,173.64 A_5_R24.1 219.2,172.96 ; 210.21,178.7 A_5_C6.2 ; A_5_C21.2 219.19,178.7 ; A_5_C14.1 214,182.49 ; 219.89,176.7 A_5_C3.2 219.21,177.43 ; A_5_SH1.8 200.1,191.13 ; A_5_SH1.8 201.23,189.5 ; A_5_SH1.8 200.1,187.87 ; A_5_SH1.8 198.97,189.5 ; 210.21,177.3 A_5_C7.2 ; A_5_C13.2 215.43,182.49
  TOP w0.4: 214.7,187.8 214.7,186.7
  TOP w0.5: A_5_C18.1 A_5_C17.2 ; A_5_C18.1 214,190.6 ; A_5_C18.1 A_5_C51.1 A_5_C50.2 A_5_C17.2 ; A_5_C17.2 215.43,190.6 ; A_5_C14.1 A_5_C13.2
  IS1 w0.3: 231.26,186.37 A_5_TB2.6 228.6,186.37 ; 205.47,170.3 A_5_SH1.2 ; A_5_SH1.2 206.6,171.43 ; A_5_SH1.2 207.73,170.3 ; 226.7,174.77 A_5_SH1.4 ; A_5_SH1.4 227.83,175.9 ; A_5_SH1.4 225.57,175.9 ; A_5_SH1.4 226.7,177.03 ; A_5_SH1.5 227.83,188.6 ; A_5_SH1.5 225.57,188.6 ; A_5_SH1.5 226.7,189.73 ; A_5_SH1.5 226.7,187.47 ; A_5_SH1.8 200.1,190.63 ; A_5_SH1.8 200.1,188.37 ; A_5_SH1.8 198.97,189.5 ; A_5_SH1.8 201.23,189.5 ; A_5_SH1.3 219.3,171.43 ; A_5_SH1.3 218.17,170.3 ; A_5_SH1.3 220.43,170.3 ; A_5_SH1.6 218.13,191.9 ; A_5_SH1.6 217,190.77 ; A_5_SH1.6 215.87,191.9 ; A_5_SH1.1 200.1,177.93 ; A_5_SH1.1 200.1,175.67 ; A_5_SH1.1 201.23,176.8 ; A_5_SH1.1 198.97,176.8 ; 204.3,190.77 A_5_SH1.7 ; A_5_SH1.7 203.17,191.9 ; A_5_SH1.7 205.43,191.9 ; 195.47,188.4 A_5_TB3.6 ; A_5_TB3.6 196.8,189.73 ; A_5_TB3.6 198.13,188.4
  IS2 w0.3: 207.73,170.3 A_5_SH1.2 205.47,170.3 ; 200.1,188.37 A_5_SH1.8 ; A_5_SH1.8 201.23,189.5 ; A_5_SH1.8 198.97,189.5 ; A_5_SH1.8 200.1,190.63 ; 215.87,191.9 A_5_SH1.6 ; A_5_SH1.6 217,190.77 ; A_5_SH1.6 218.13,191.9 ; A_5_SH1.4 227.83,175.9 ; A_5_SH1.4 226.7,174.77 ; A_5_SH1.4 225.57,175.9 ; A_5_SH1.4 226.7,177.03 ; A_5_TB3.6 198.13,188.4 ; A_5_TB3.6 196.8,189.73 ; A_5_TB3.6 195.47,188.4 ; 225.57,188.6 A_5_SH1.5 ; A_5_SH1.5 226.7,189.73 ; A_5_SH1.5 227.83,188.6 ; A_5_SH1.5 226.7,187.47 ; 220.43,170.3 A_5_SH1.3 218.17,170.3 ; 203.17,191.9 A_5_SH1.7 ; A_5_SH1.7 205.43,191.9 ; A_5_SH1.7 204.3,190.77 ; 228.6,186.37 A_5_TB2.6 231.26,186.37 ; 200.1,175.67 A_5_SH1.1 ; A_5_SH1.1 201.23,176.8 ; A_5_SH1.1 200.1,177.93
  BOTTOM w0.3: 228.55,186.37 A_5_TB2.6 231.31,186.37 ; 225.57,175.9 A_5_SH1.4 ; A_5_SH1.4 226.7,174.27 ; A_5_SH1.4 227.83,175.9 ; A_5_SH1.4 226.7,177.53 ; A_5_SH1.6 218.63,191.9 ; A_5_SH1.6 215.37,191.9 ; A_5_SH1.6 217,190.77 ; A_5_SH1.2 206.6,171.43 ; A_5_SH1.2 208.23,170.3 ; A_5_SH1.2 204.97,170.3 ; 202.67,191.9 A_5_SH1.7 ; A_5_SH1.7 205.93,191.9 ; A_5_SH1.7 204.3,190.77 ; A_5_SH1.8 200.1,191.13 ; A_5_SH1.8 201.23,189.5 ; A_5_SH1.8 198.97,189.5 ; A_5_SH1.8 200.1,187.87 ; A_5_SH1.3 220.93,170.3 ; A_5_SH1.3 219.3,171.43 ; A_5_SH1.3 217.67,170.3 ; 226.7,186.97 A_5_SH1.5 ; A_5_SH1.5 226.7,190.23 ; A_5_SH1.5 227.83,188.6 ; A_5_SH1.5 225.57,188.6 ; A_5_SH1.1 201.23,176.8 ; A_5_SH1.1 198.97,176.8 ; A_5_SH1.1 200.1,175.17 ; A_5_SH1.1 200.1,178.43 ; A_5_TB3.6 198.18,188.4 ; A_5_TB3.6 196.8,189.78 ; A_5_TB3.6 195.42,188.4
  vias: v2(195.1,189.85) v2(195.1,187.35) v2(195.1,184.85) v2(195.1,182.35) v2(195.1,179.85) v2(195.1,177.35) v2(195.1,174.85) v2(195.1,172.35) v2(195.1,169.85) v2(196.5,173.5) v2(196.5,171) v2(197.6,169.85) v2(197.65,172.25) v2(198.4,190.35) v2(198.6,186.75) v2(198.6,184.4) v2(198.6,182) v2(198.6,179.05) v2(198.6,175) v2(198.8,170.9) v2(198.95,192.55) v2(200.1,191.85) v2(200.1,187.3) v2(200.1,185.5) v2(200.1,183) v2(200.1,180.55) v2(200.1,173.5) v2(200.1,170.35) v2(200.95,192.6) v2(201.45,174.65) v2(201.65,190.5) v2(201.65,188) v2(201.65,185.5) v2(201.65,183.6) v2(202.25,178.5) v2(202.15,172.55) v2(202.45,175.8) v2(202.4,170.3) v2(202.6,192.6) v2(202.6,180.5) v2(203.05,189.3) v2(203.05,186.8) v2(203.05,184.3) v2(203.4,174.3) v2(204.15,190.5) v2(204.15,188) v2(204.15,185.5) v2(204.15,183) v2(204.15,181.1) v2(204.15,170.3) v2(204.5,176.15) v2(204.55,172.5) v2(204.9,178.15) v2(205.4,189.25) v2(205.4,186.75) v2(205.4,184.25) v2(205.4,181.75) v2(205.6,179.7) v2(205.75,174.3) v2(206,192.65) v2(206.25,187.55) v2(206.25,185.45) v2(206.45,189.3) v2(206.65,183) v2(206.65,180.5) v2(207.2,176) v2(207.2,174.3) v2(207.3,192.6) v2(207.3,172.5) v2(207.45,177.7) v2(207.95,189.05) v2(207.95,181.6) v2(208,187.45) v2(208,179.55) v2(208.4,190.7) v2(208.55,170.3) v2(208.65,183.5) v2(208.8,192.65) v2(209.15,180.5) v2(209.6,181.75) v2(209.65,183.5) v2(209.85,174.3) v2(209.8,172.5) v2(209.9,187.8) v2(209.95,176.2) v2(210.4,190.6) v2(210.9,192.55) v2(210.9,172.4) v2(211.25,187.8) v2(211.15,170.25) v2(212.2,191.9) v2(212.7,190.55) v2(213.25,192.6) v2(213.55,170.3) v2(214,183.55) v2(214,182.7) v2(214.6,191.9) v2(214.75,190.45) v2(215.3,192.65) v2(215.4,183.55) v2(215.4,182.7) v2(216.1,170.3) v2(217.15,190.5) v2(217.55,172.55) v2(218.2,187.75) v2(218.55,192.65) v2(219.05,190.5) v2(219.45,177.7) v2(219.5,187.75) v2(219.75,183.5) v2(219.8,181.7) v2(219.8,172.6) v2(220.6,192.6) v2(220.65,180.5) v2(220.65,176.7) v2(220.75,183.5) v2(221,190.5) v2(221.25,173) v2(221.4,189.15) v2(221.4,187.5) v2(221.5,191.9) v2(221.65,181.45) v2(222.45,171.4) v2(222.6,192.6) v2(222.7,177.85) v2(222.75,183) v2(222.75,180.5) v2(222.95,189.7) v2(223.05,186.7) v2(223.05,184.6) v2(223.4,170.3) v2(223.5,175.9) v2(224.05,191.9) v2(224.2,190.65) v2(224.2,188.7) v2(224.2,186.2) v2(224.2,183.7) v2(224.2,181.2) v2(224.65,174.85) v2(224.95,171.4) v2(225,179.55) v2(225.45,189.95) v2(225.45,187.45) v2(225.45,184.95) v2(225.45,182.45) v2(225.55,192.65) v2(226.65,191.85) v2(226.7,186.3) v2(226.7,183.7) v2(226.7,181.2) v2(226.7,179.1) v2(226.7,172.1) v2(226.7,170.3) v2(228.15,192.65) v2(228.15,190.15) v2(228.15,187.65) v2(228.15,185.15) v2(228.15,182.4) v2(228.15,180) v2(228.2,177.2) v2(228.2,173.8) v2(228.85,171.9) v2(228.85,169.85) v2(231.35,169.85) v2(231.8,177.65) v2(231.8,175.15) v2(231.9,192.65) v2(231.9,190.15) v2(231.9,187.65) v2(231.9,185.15) v2(231.9,182.65) v2(231.9,180.15) v2(231.9,172.95) v2(233.15,191.4) v2(233.15,188.9) v2(233.15,186.4) v2(233.15,183.9) v2(233.15,181.4) v2(233.15,178.9) v2(234.4,192.65) v2(234.4,190.15) v2(234.4,187.65) v2(234.4,185.15) v2(234.4,182.65) v2(234.4,180.15) v2(234.4,177.65) v2(234.4,175.15) v2(234.4,172.65) v3(213.7,176.8) v3(213.7,175.8) v3(213.95,172.4) v3(213.95,171.95) v3(214.2,175.8) v3(214.4,172.4) v3(214.4,171.95) v3(215,173.85) v3(215,173.3) v3(215.2,177.8) v3(215.45,173.85) v3(215.45,173.3) v3(215.7,177.3) v3(215.7,176.3)
